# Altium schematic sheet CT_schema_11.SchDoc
size 274 x 160 mm
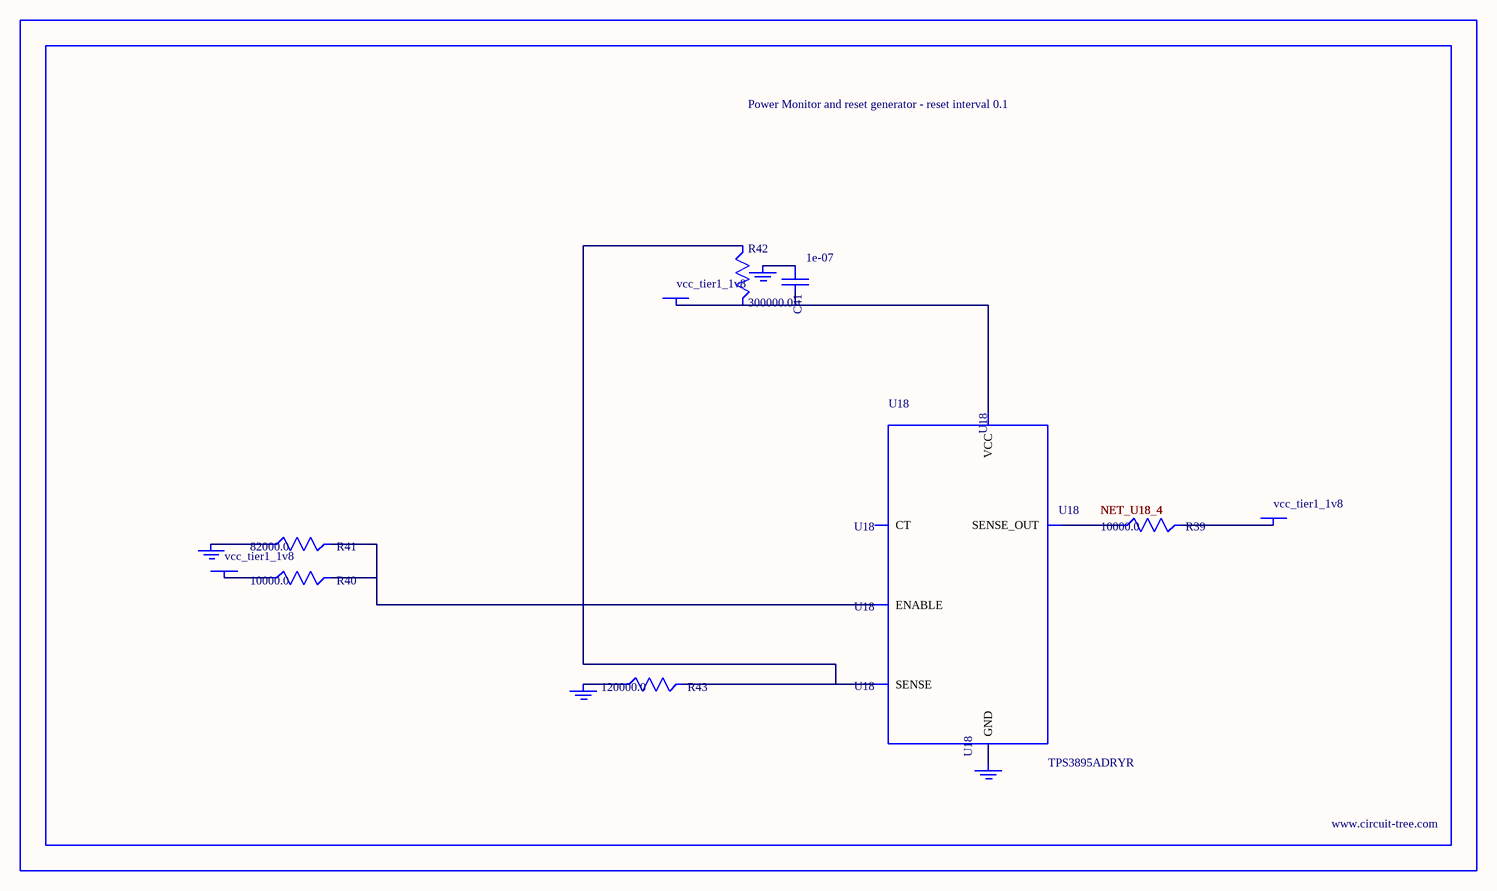
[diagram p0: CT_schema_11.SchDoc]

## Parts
BORDER10  (no value)
C41  1e-07  [C0402]
GND_INSTANCE_10_0  (no value)
GND_INSTANCE_10_1  (no value)
GND_INSTANCE_10_2  (no value)
GND_INSTANCE_10_3  (no value)
POWER_INSTANCE_10_0  vcc_tier1_1v8
POWER_INSTANCE_10_1  vcc_tier1_1v8
POWER_INSTANCE_10_2  vcc_tier1_1v8
R39  10000.0  [R0603]
R40  10000.0  [R0603]
R41  82000.0  [R0603]
R42  300000.0  [R0603]
R43  120000.0  [R0603]
U18  TPS3895ADRYR  [SON-6]

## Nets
NetC41_1: C41.1 GND_INSTANCE_10_2.0(GND)
NetC41_2: C41.2 POWER_INSTANCE_10_2.0(PWR) R42.2 U18.6(VCC)
NetGND_INSTANCE_10_0_0: GND_INSTANCE_10_0.0(GND) R41.1
NetGND_INSTANCE_10_1_0: GND_INSTANCE_10_1.0(GND) R43.1
NetGND_INSTANCE_10_3_0: GND_INSTANCE_10_3.0(GND) U18.2(GND)
NetPOWER_INSTANCE_10_0_0: POWER_INSTANCE_10_0.0(PWR) R40.1
NetPOWER_INSTANCE_10_1_0: POWER_INSTANCE_10_1.0(PWR) R39.2
NetR39_1: R39.1 U18.4(SENSE_OUT)
NetR40_2: R40.2 R41.2 U18.1(ENABLE)
NetR42_1: R42.1 R43.2 U18.3(SENSE)

Not connected (* = marked no-connect by the designer): U18 5(CT)

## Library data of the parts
BORDER10 = BORDER_PAGE10
C41 = C0402C104K3RACTU
GND_INSTANCE_10_0-GND_INSTANCE_10_3 = GND
POWER_INSTANCE_10_0-POWER_INSTANCE_10_2 = PWR
R39 R40 = RC0603JR-0710KL
R41 = RC0603JR-0782KL
R42 = RC0603JR-07300KL
R43 = RC0603JR-07120KL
